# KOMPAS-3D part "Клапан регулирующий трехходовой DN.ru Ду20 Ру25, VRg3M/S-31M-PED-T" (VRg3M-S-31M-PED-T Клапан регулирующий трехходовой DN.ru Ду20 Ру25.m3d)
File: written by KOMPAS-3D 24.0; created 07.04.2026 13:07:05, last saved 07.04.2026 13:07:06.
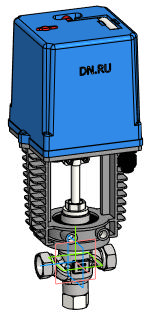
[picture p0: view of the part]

Document properties: Автор: DN.RU; Полное имя файла: D:\PROJECT CAD\DN.RU\...197(ACTUALE). VRg3M-S-31M-PED-T Клапан регулирующий трехходовой DN.ru\Исходники\DN20\VRg3M-S-31M-PED-T Клапан регулирующий трехходовой DN.ru Ду20 Ру25.m3d

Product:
- Body: Твердое тело1  | qty 1
    Масса: 18.849
- Part/product: Клапан регулирующий трехходовой DN.ru Ду20 Ру25  | designation VRg3M/S-31M-PED-T
    Масса: 3.1
    Раздел спецификации: Прочие изделия
    Комментарий: D230-11264
    Примечание: D230-11264
    additional columns: Типовые

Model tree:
1. Твердое тело1  (labels: Твердое тело1)

Expressions: VRg3M/S-31M-PED-T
